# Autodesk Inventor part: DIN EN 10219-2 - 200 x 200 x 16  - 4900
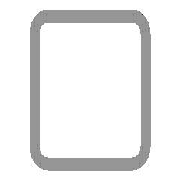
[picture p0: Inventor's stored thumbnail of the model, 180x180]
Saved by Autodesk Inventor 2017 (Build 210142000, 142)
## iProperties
IsCustomPart: 1
Created: 2016-02
Part Number: DIN EN 10219-2 - 200 x 200 x 16  - 4900
Material: Steel, Mild
Description: Cold formed welded structural hollow sections of non-alloy and fine grain structural steel
Document SubType Name: Modeling
Standard: DIN
Designer: iusti
Standard Revision: 2006-07
Standards Organization: DIN
Language: en-US
Size Designation: 200 x 200 x 16
Categories: <MemberInstance><Categories><Category DisplayName="Structural Shapes" InternalName="089c4875-fa83-4c05-b084-43b9cc11f5ed" Mnemonic="GRDR"><CategoryParameter Dis
Stock Number: 200 x 200 x 16
Density: 7.85 g/cm^3
Appearance: Semi-Polished
Mass: 410700 g
Surface Area: 65611.6 cm^2
Volume: 52318.5 cm^3
_CCFamilyMember: 103
_CCFamilyDisplayName: DIN EN 10219-2 (Square Hollow Section - Cold Formed) - Cold formed welded structural hollow sections of non-alloy and fine grain structural steel
_FrameMemberDoc: Frame Member File
_Version: 15.0.0
_GetPNFromCC: 1
G_L: 4900.000 mm
G_W: 200.000 mm
G_H: 200.000 mm
+0D5BCBA2-F1B2-4388-A824-2414ADB6311C+CUTDETAIL1: Cut
Author: iusti
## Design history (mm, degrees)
node "Start plane"
node "End plane"
sketch "Sketch"
  geometry: L1 (-100, -52)-(-100, 52); L2 (-52, 100)-(52, 100); L3 (100, 52)-(100, -52); L4 (52, -100)-(-52, -100); L5 (-52, 84)-(52, 84); L6 (84, 52)-(84, -52); L7 (52, -84)-(-52, -84); L8 (-84, -52)-(-84, 52); L9 (0, 153.918)-(0, -153.918) reference; L10 (-153.918, 0)-(153.918, 0) reference; A1 r 48 centre (-52, -52) between (-100, -52) and (-52, -100); A2 r 48 centre (-52, 52) between (-52, 100) and (-100, 52); A3 r 48 centre (52, 52) between (100, 52) and (52, 100); A4 r 48 centre (52, -52) between (52, -100) and (100, -52); A5 r 32 centre (-52, 52) between (-52, 84) and (-84, 52); A6 r 32 centre (52, 52) between (84, 52) and (52, 84); A7 r 32 centre (52, -52) between (52, -84) and (84, -52); A8 r 32 centre (-52, -52) between (-84, -52) and (-52, -84)
  constraints: 16 end point, 16 point on circle, 8 centre point, 8 tangent, 4 parallel, 3 equal radius, 2 perpendicular, 7 other
  dimensions: "d7" = 48 radius of A1 (= G_IR); "d10" = 200 distance between parallel lines of L2 L4 (= G_H); "d11" = 200 distance between parallel lines of L1 L3 (= G_W); "d12" = 16 distance between parallel lines of L3 L6 (= G_T); "d15" = 100 distance between parallel lines of L2 L10 (= 0.5 x d10); "d16" = 100 distance between parallel lines of L9 L3 (= 0.5 x d11)
extrude "Body" new body sketch "Sketch" stored distance "d3" = 4900 (= G_L); taper "d4" = 0 deg
node "Driven Length"
  sketch "Sketch3"
    geometry: L1 (0, 0)-(10, 0) reference
    constraints: 2 end point, 1 horizontal
  workplane "Work Plane3"
  sketch "Sketch4"
    geometry: L1 (-2, 100)-(12, 100) reference; L2 (-2, 5000)-(12, 5000) reference
    dimensions: "d18" = 4900 distance between parallel lines of L1 L2 (derived)
workplane "Work Plane4"
split "Split1"
body "Solid1"
other parameters: "G_W" = 200 [user parameter; used in 1 equation term], "G_H" = 200 [user parameter; used in 1 equation term], "G_T" = 16 [user parameter; used in 1 equation term], "G_IR" = 48 [user parameter; used in 1 equation term], "G_L" = 4900 (= d18) [user parameter; used in 1 equation term], "G_OFFSET_END" = 0 [user parameter; used in 1 equation term], "d17" = 90 deg
